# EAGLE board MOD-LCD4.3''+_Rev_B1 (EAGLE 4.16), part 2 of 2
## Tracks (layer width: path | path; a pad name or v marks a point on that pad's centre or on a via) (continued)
MCIDAT0  (via drill 0.4) (continued)
  Route2 0.25: v95.25,45.45 96.2,44.5 96.2,38.5 96.7,38 96.7,29.6 97.1,29.2 97.1,22.66 98.3,21.46 v98.3,16.89
  Bottom 0.25: v95.25,45.45 94.55,46.15 91.25,46.15 83,54.4 79.6,54.4 79.2,54.8 U2.171
  Bottom 0.508: MICRO_SD.7 98.3,15.41 v98.3,16.89 98.3,17.14 97.24,18.2 R14.2
MCIDAT1  (via drill 0.4)
  Top 0.25: v72.4,60.85 72.8,60.85 74.05,59.6 86.6,59.6 87.1,59.1 91.2,59.1 v91.6,59.5
  Route2 0.25: v91.6,59.5 91.9,59.2 91.9,52.1 96.7,47.3 96.7,38.7 97.2,38.2 97.2,29.8 97.6,29.4 97.6,22.9 99.19,21.31 99.19,17.14 v99.44,16.89
  Bottom 0.25: U2.153 73.3,62.4 72.4,61.5 v72.4,60.85
  Bottom 0.508: R18.2 99.44,18.03 v99.44,16.89 99.44,15.39 MICRO_SD.8
MCIDAT2  (via drill 0.4)
  Route2 0.25: v92.33,17.14 93,17.82 93,49.6 90.6,52 v90.6,58.35
  Bottom 0.25: U2.163 78.3,58.8 79,58.1 86.1,58.1 86.7,57.5 89.75,57.5 v90.6,58.35
  Bottom 0.508: MICRO_SD.1 91.73,16.55 v92.33,17.14 92.58,17.4 92.58,18.04 R20.2
MCIDAT3  (via drill 0.4)
  Route2 0.25: v90.81,17.02 90.81,17.65 92.5,19.35 92.5,49.4 89.75,52.15 89.75,59.8 v89.7,59.85
  Bottom 0.25: U2.157 78.8,61.8 80,60.6 88.95,60.6 v89.7,59.85 | 92.83,14.47 92.33,13.97 91.19,13.97 90.81,14.35 v90.81,17.02
  Bottom 0.508: v90.81,17.02 90.81,18.09 R9.2 | 92.83,14.47 MICRO_SD.2
MCIPWR  (via drill 0.4)
  Top 0.25: v93.7,59.35 93.7,60 92,61.7 85.4,61.7 84.8,61.1 76.8,61.1 v75.85,62.05
  Bottom 0.25: v75.85,62.05 74.8,63.1 U2.156
  Bottom 0.4: R6.2 R8.2 92.5,53.6 92.5,58.15 v93.7,59.35
MISO  (via drill 0.4, 0.6)
  Top 0.25: v58.45,60.5 58.15,60.8 56.8,60.8 56.2,61.4 47.55,61.4 46.95,62 36.4,62 34.8,60.4 7.2,60.4 4.3,57.5 4.3,55.8 2.3,53.8 2.3,49.7 4.5,47.5 v11.7,47.5
  Bottom 0.25: v58.45,60.5 58.45,61.83 59.8,63.17 U2.126
  Bottom 0.4: 11.16,43.96 11.7,44.5 v11.7,47.5
  Bottom 1: 11.16,43.96 UEXT.7
MMC_VDD  (via drill 0.4)
  Route2 0.25: v97.03,21.34 96.9,21.21 v96.9,16.89
  Bottom 0.508: C6.2 98.17,26.2 98.17,23.87 L1.1 97.03,22.73 v97.03,21.34 | v96.9,16.89 95.38,16.89 95.03,16.54 MICRO_SD.4
MOSI  (via drill 0.4, 0.6)
  Top 0.25: v4.5,45 4.5,45.8 1.3,49 1.3,54.4 3.1,56.2 3.1,58.1 6.4,61.4 34.4,61.4 36,63 47.2,63 47.8,63.6 52.9,63.6 53.63,62.87 57.84,62.87 v58.1,62.6
  Bottom 0.25: v58.1,62.6 58.8,63.3 U2.124
  Bottom 0.5: UEXT.8 4.06,43.96 4.5,44.4 v4.5,45
N$1  (via drill 0.4)
  Top 0.4: v94.9,62.4 94.9,61 96.5,59.4 v97.9,59.4
  Bottom 0.25: 82.8,63.9 U3.2
  Bottom 0.4: v97.9,59.4 98.4,58.9 L3.1 | v94.9,62.4 94.3,61.8 83.5,61.8 82.6,62.7 82.6,63.7 82.8,63.9
  Bottom 1.016: C50.2 96.56,54.44 97.6,53.4 L3.1
N$2
  Bottom 0.25: U2.44 53.3,28.6 52.67,27.98 52.38,27.98 R36.2
  Bottom 0.8: C12.2 47.2,24.5 48.5,24.5 | 48.5,24.5 48.9,24.5 R36.2 | Q1.1 48.5,24.5
N$3
  Bottom 0.4: VDDA_E.2 L5.2
N$4  (via drill 0.4, 0.6)
  Top 0.4: v54.35,17.9 54.8,17.45 70.55,17.45 71.9,16.1 82.18,16.1 82.97,16.89 86.55,16.89 v90.73,21.07
  Bottom 0.25: v90.73,21.07 90.5,21.3 LCD.2
  Bottom 0.4: T3.3 55.55,18.3 54.75,18.3 v54.35,17.9
N$5
  Bottom 0.6: R5.2 56.9,14.8 | 56.9,14.8 R11.2 | 56.9,14.8 T3.1
N$6
  Bottom 0.6: R11.1 59.95,13.1 T4.3
N$7
  Bottom 0.25: R36.1 52.3,29.6 U2.46
  Bottom 0.8: 48.5,28.8 Q1.2 | C14.2 48.5,28.8 | 48.5,28.8 49.9,28.8 50.4,29.3 R36.1
N$8
  Bottom 0.25: Q2.2 58.3,30.73 U2.34
  Bottom 0.6: C15.2 58.3,25.7 57.87,26.13 Q2.2
N$9
  Bottom 0.25: U2.36 57.3,32.8 55.8,31.3 55.8,30.77 Q2.1
  Bottom 0.6: Q2.1 55.33,26.43 54.6,25.7 C16.2
N$10
  Bottom 0.6: 59.3,17.3 T4.1 | R39.2 59.3,17.3 | 59.3,17.3 R21.1
N$11
  Bottom 0.5: 6.2,61.78 3.3V_UEXT_E.1 | UEXT.1 7.3,51.58 7.3,59.8 7.2,59.9 R2.2
  Bottom 0.762: R1.2 3.05,59.9 3.05,59.91 R23.2 5.21,59.91 5.21,59.9 R2.2
  Bottom 0.8: R2.2 6.2,61.78
N$12  (via drill 0.4)
  Top 0.25: v103.85,57.7 103.75,57.6 102.7,57.6 102,58.3 99.65,58.3 99.45,58.1 93.05,58.1 92.4,58.75 92.4,59.9 91.6,60.7 85.8,60.7 85.2,60.1 76.08,60.1 74.58,61.6 69.2,61.6 v68.42,60.83
  Bottom 0.25: v103.85,57.7 104.55,57 105.35,57 105.53,56.83 | v68.42,60.83 68.8,61.2 U2.144
  Bottom 0.6: 105.53,56.83 EXT1.6
N$13  (via drill 0.4, 0.6)
  Top 0.25: v66.92,59.83 67.72,59.83 67.95,59.6 71.1,59.6 72.1,58.6 86.1,58.6 87.6,57.1 99,57.1 99.3,56.8 103.2,56.8 103.38,56.98 105.38,56.98 106.8,55.55
  Top 0.4: 106.8,55.55 v113.3,55.55
  Bottom 0.25: v66.92,59.83 67.2,60.1 67.2,61.15 66.8,61.55 U2.140
  Bottom 0.4: v113.3,55.55 EXT1.7
N$14  (via drill 0.4)
  Top 0.25: v105.03,56.05 104.58,56.5 103.6,56.5 103.4,56.3 99.1,56.3 98.8,56.6 87.4,56.6 85.9,58.1 71.9,58.1 70.9,59.1 66.6,59.1 66.35,59.35 51.55,59.35 v50.8,60.1
  Bottom 0.25: v50.8,60.1 U2.108
  Bottom 0.6: v105.03,56.05 105.52,55.55 EXT1.8
N$15  (via drill 0.4, 0.6)
  Top 0.25: v49.1,54.4 49.9,53.6 71.4,53.6 73.4,55.6 98.3,55.6 98.6,55.3 103.4,55.3 103.7,55 106.28,55 107,54.28
  Top 0.4: 107,54.28 v113.3,54.28
  Bottom 0.25: U2.91 48.2,55.3 v49.1,54.4
  Bottom 0.4: v113.3,54.28 EXT1.9
N$16
  Bottom 0.25: 94.1,47.7 T2.1
  Bottom 0.4: 94.1,47.7 R15.2 91.9,48 91.5,48 91.1,48.4 91.1,50.5 R8.1
N$17  (via drill 0.4)
  Top 0.25: v104.03,55.73 103.95,55.8 98.9,55.8 98.6,56.1 73.2,56.1 71.2,54.1 55.5,54.1 v53.5,56.1
  Bottom 0.25: v53.5,56.1 51.5,58.1 50.1,58.1 48.9,59.3 U2.99
  Bottom 0.6: EXT1.10 105.28,54.28 104.03,55.55 v104.03,55.73
N$18  (via drill 0.4, 0.6)
  Top 0.25: 107.4,53.02 105.92,54.5 103.5,54.5 103.2,54.8 98.4,54.8 98.1,55.1 73.6,55.1 71.6,53.1 53,53.1 52.45,52.55 v51.15,52.55
  Top 0.4: 107.4,53.02 v113.3,53.02
  Route2 0.25: v48.8,43.3 48.5,43.6 48.5,49.9 v51.15,52.55
  Bottom 0.25: U2.67 v48.8,43.3
  Bottom 0.4: v113.3,53.02 EXT1.11
N$19  (via drill 0.4)
  Top 0.25: v51.85,50.35 52.55,50.35 53.8,51.6 72.2,51.6 74.2,53.6 97.5,53.6 97.8,53.3 102.6,53.3 102.9,53 104.1,53 v104.45,52.65
  Bottom 0.25: v51.85,50.35 51.1,49.6 50,49.6 49.3,50.3 U2.81
  Bottom 0.6: v104.45,52.65 104.81,53.02 EXT1.12
N$20  (via drill 0.4, 0.6)
  Top 0.25: 108.04,51.74 107.86,51.74 105.6,54 103.3,54 103,54.3 98.2,54.3 97.9,54.6 73.8,54.6 71.8,52.6 53.2,52.6 52.4,51.8 50,51.8 v49.5,52.3
  Top 0.4: 108.04,51.74 v113.3,51.74
  Bottom 0.25: U2.85 v49.5,52.3
  Bottom 0.4: v113.3,51.74 EXT1.13
N$21  (via drill 0.4)
  Top 0.25: v104.7,51.6 104.6,51.5 103,51.5 102.2,52.3 97.3,52.3 97,52.6 74.6,52.6 72.6,50.6 60.8,50.6 v60.4,50.2
  Bottom 0.25: U2.64 48,41.8 48.3,41.5 51.4,41.5 54.5,44.6 54.5,46.3 58.4,50.2 v60.4,50.2
  Bottom 0.6: EXT1.14 104.84,51.74 v104.7,51.6
N$22  (via drill 0.4, 0.6)
  Top 0.25: 108.4,50.48 105.38,53.5 103.1,53.5 102.8,53.8 98,53.8 97.7,54.1 74,54.1 72,52.1 53.5,52.1 52.6,51.2 43.96,51.2 43.66,50.9 40.3,50.9
  Top 0.254: v37.4,48.2 38.26,49.06 39.16,49.06 39.85,49.75 39.85,50.45 40.3,50.9
  Top 0.4: 108.4,50.48 v113.3,50.48
  Route2 0.254: v36.8,35.8 36.8,41.9 37.8,42.9 37.8,44.9 37.4,45.3 v37.4,48.2
  Bottom 0.254: U2.54 44.5,36.8 43.7,36 38.8,36 38.6,35.8 v36.8,35.8
  Bottom 0.4: v113.3,50.48 EXT1.15
N$23  (via drill 0.4)
  Top 0.25: v56.8,47.4 57.5,48.1 60.8,48.1 61.3,47.6 67.9,47.6 68.83,48.52 84.03,48.52 84.6,49.1 97,49.1 97.9,48.2 102.83,48.2 v102.95,48.33
  Bottom 0.25: U2.57 49,38.3 55.3,44.6 55.3,45.9 v56.8,47.4 | v102.95,48.33 102.95,49.75 103.67,50.48
  Bottom 0.6: 103.67,50.48 EXT1.16
N$24  (via drill 0.4, 0.6)
  Top 0.25: v61.33,49.8 61.62,50.1 76.25,50.1 77.75,51.6 96.6,51.6 98.5,49.7 101.2,49.7 101.8,50.3 107.32,50.3 108.42,49.2 108.49,49.2
  Top 0.4: 108.49,49.2 v113.3,49.2
  Bottom 0.25: U2.47 51.8,40.27 v61.33,49.8
  Bottom 0.4: v113.3,49.2 EXT1.17
N$25  (via drill 0.4)
  Top 0.25: v62.2,48.35 67.85,48.35 68.5,49 83.8,49 84.35,49.55 97.25,49.55 98.1,48.7 101.8,48.7 102.2,49.1 103.25,49.1 103.65,48.7 104.3,48.7 v105.1,49.5
  Bottom 0.25: U2.31 59.8,34.8 59.5,35.1 59.5,36 59.8,36.3 60.7,36.3 61.5,37.1 61.5,39.8 61.3,40 61.3,46.9 62.2,47.8 v62.2,48.35
  Bottom 0.6: v105.1,49.5 105.39,49.2 EXT1.18
N$26  (via drill 0.4, 0.6)
  Top 0.25: v60.38,47.38 60.65,47.1 68.2,47.1 69.15,48.05 84.15,48.05 84.7,47.5 85.5,47.5 86.1,48.1 96.6,48.1 97.6,47.1 105.54,47.1 106.37,47.94 108.56,47.94
  Top 0.4: 108.56,47.94 v113.3,47.94
  Bottom 0.25: U2.39 55.8,35.2 56,35.4 56,36.2 55.6,36.6 55.15,36.6 54.4,37.35 54.4,41.4 v60.38,47.38
  Bottom 0.4: v113.3,47.94 EXT1.19
N$27  (via drill 0.4)
  Top 0.25: v79.42,49.77 83.83,49.77 84.05,50 97.5,50 98.3,49.2 101.5,49.2 101.9,49.6 103.8,49.6 v103.9,49.5
  Route2 0.25: v65.2,61 65.6,61 66.25,61.65 74.65,61.65 78.7,57.6 78.7,50.5 v79.42,49.77
  Bottom 0.25: v65.2,61 64.8,61.4 64.8,62.3 65.3,62.8 U2.137
  Bottom 0.6: v103.9,49.5 103.9,49.4 105.36,47.94 EXT1.20
N$28  (via drill 0.4, 0.6)
  Top 0.25: v68.05,62.4 68.3,62.4 68.7,62.8 78.6,62.8 78.8,62.6 93.5,62.6 94.1,63.2 98.1,63.2 98.3,63 v103.6,63
  Route2 0.25: v113.3,46.66 111.94,46.66 108.1,50.5 108.1,57.4 103.6,61.9 v103.6,63
  Bottom 0.25: v68.05,62.4 68.3,62.65 U2.143
  Bottom 0.4: v113.3,46.66 EXT1.21
N$29
  Bottom 0.508: 25.71,19.22 25.78,19.29 25.78,19.3 24.64,19.3 24.38,19.05 | VR2.1 21.59,16.89 22.23,16.89
  Bottom 0.559: VR2.1 21.59,16.13 21.84,16.13
  Bottom 1.016: L2.1 26.11,16.13 23.37,16.13 | 21.84,16.13 23.37,16.13 | 23.37,16.13 C51.1 25.71,19.22 26.04,19.22 | 26.04,19.3 D6.1 26.04,19.22 | 26.04,19.22 26.07,19.18
  Bottom 1.27: 25.71,19.22 25.4,19.22 25.4,16.38 24.38,16.38 24.38,19.05 | 22.23,16.89 23.24,16.89
N$30  (via drill 0.4)
  Route2 0.25: v95.8,61.7 95.8,61.1 96.65,60.25 99.65,60.25 100.7,59.2 100.7,51.8 v100.97,51.52
  Bottom 0.25: U2.151 72.3,64.7 73.1,65.5 74.8,65.5 77.8,62.5 78.85,62.5 80.25,61.1 95.2,61.1 v95.8,61.7 | v100.97,51.52 101.17,51.52 101.7,51 101.7,47.3 102.33,46.66 105.41,46.66
  Bottom 0.6: 105.41,46.66 EXT1.22
N$31
  Bottom 0.559: R29.2 47.62,2.96 47.62,2.86 U5.3
  Bottom 1.016: R29.2 48.51,2.96 48.51,2.92 R26.1
N$32  (via drill 0.4, 0.6)
  Route2 0.25: v113.3,45.4 111.91,45.4 107.4,49.9 107.4,57.1 103,61.5 102.1,61.5 101.7,61.1 v96.85,61.1
  Bottom 0.25: U2.161 78.7,59.8 79.4,59.1 86.5,59.1 87,58.6 88.1,58.6 88.6,59.1 90.1,59.1 91.6,60.6 96.35,60.6 v96.85,61.1
  Bottom 0.4: v113.3,45.4 EXT1.23
N$33  (via drill 0.4)
  Top 0.25: v104.9,45.8 104.6,46.1 97.2,46.1 96.65,46.65 84.85,46.65 84.1,47.4 73.35,47.4 v73.25,47.3
  Route2 0.25: v73.25,47.3 73,47.55 73,53.2 74.15,54.35 v74.15,56.85
  Bottom 0.25: U2.167 76.17,56.8 75.47,56.1 74.4,56.1 74.15,56.35 v74.15,56.85
  Bottom 0.6: v104.9,45.8 105.31,45.4 EXT1.24
N$34  (via drill 0.4, 0.6)
  Top 0.25: v87.75,47.38 87.97,47.6 96.4,47.6 97.4,46.6 105.6,46.6 108.08,44.12 109.38,44.12
  Top 0.4: 109.38,44.12 v113.3,44.12
  Bottom 0.25: U2.175 79.6,52.8 82.4,50 86,50 87.75,48.25 v87.75,47.38
  Bottom 0.4: v113.3,44.12 EXT1.25
N$35
  Bottom 0.61: R54.2 15.88,17.02 17.27,17.02 17.78,16.51 VR2.4
  Bottom 1.016: R50.1 15.88,18.92 R54.2
N$36  (via drill 0.4)
  Top 0.25: v73.3,46.3 78,46.3 78.6,46.9 83.88,46.9 84.58,46.2 96.4,46.2 97,45.6 103.6,45.6 v104.3,44.9
  Bottom 0.25: U2.195 76.3,42.8 76.1,42.6 76.1,41.5 75.2,40.6 74.6,40.6 72.4,42.8 72.4,45.4 v73.3,46.3
  Bottom 0.4: v104.3,44.9 104.7,44.5 105.3,44.5 105.67,44.12
  Bottom 0.6: 105.67,44.12 EXT1.26
N$37  (via drill 0.4, 0.6)
  Top 0.25: v49.05,42.3 50.79,40.56 79.24,40.56 80.6,39.2 87.1,39.2 87.5,39.6 102.4,39.6 103.85,41.05 107.35,41.05 109.16,42.85 109.5,42.85
  Top 0.4: 109.5,42.85 v113.3,42.85
  Bottom 0.25: U2.65 v49.05,42.3
  Bottom 0.4: v113.3,42.85 EXT1.27
N$38  (via drill 0.4)
  Top 0.25: v104.42,40.3 103.8,40.3 102.6,39.1 87.7,39.1 87.3,38.7 80.4,38.7 79.04,40.06 50.26,40.06 47.8,37.6 v45.7,37.6
  Bottom 0.25: EXT1.28 105.75,42.85 105.1,42.2 105.1,41.6 104.42,40.92 v104.42,40.3 | v45.7,37.6 45.7,38.1 46.4,38.8 U2.58
N$39  (via drill 0.4, 0.6)
  Top 0.25: 109.63,41.59 108.69,41.59 105.67,38.58 103.58,38.58 103.1,38.1 88.1,38.1 87.7,37.7 80,37.7 78.64,39.06 52.26,39.06 v51,37.8
  Top 0.4: 109.63,41.59 v113.3,41.59
  Bottom 0.25: U2.56 v51,37.8
  Bottom 0.4: v113.3,41.59 EXT1.29
N$40  (via drill 0.4)
  Top 0.25: v104.45,39.3 103.55,39.3 102.85,38.6 87.9,38.6 87.5,38.2 80.2,38.2 78.84,39.56 51.46,39.56 v48.9,37
  Bottom 0.25: EXT1.30 105.78,41.59 105.2,41 105.2,39.8 104.7,39.3 v104.45,39.3 | U2.55 48.6,37.3 v48.9,37
N$41  (via drill 0.4, 0.6)
  Top 0.25: v74.2,37.75 78.4,37.75 79.45,36.7 88.15,36.7 88.55,37.1 105,37.1 108.22,40.31 109.63,40.31
  Top 0.4: 109.63,40.31 v113.3,40.31
  Bottom 0.25: v74.2,37.75 75.25,38.8 U2.203
  Bottom 0.4: v113.3,40.31 EXT1.31
N$42
  Bottom 0.5: RM2.3.2 35.38,41.22 34.99,41.61
  Bottom 1: JTAG.17 34.99,41.61
N$43
  Bottom 0.4: 96.3,46.7 91.5,46.7 90.1,48.1 R6.1 | 96.3,46.7 R7.2 | 96.3,46.7 96.3,48.45 T2.3
N$44  (via drill 0.4)
  Top 0.25: v73.08,35.75 73.33,36 77.92,36 78.72,35.2 88.8,35.2 89.2,35.6 108.2,35.6 v109.6,34.2
  Bottom 0.25: U2.5 72.8,34 | 72.8,34 72.8,33.9 | 72.8,34 72.8,35.48 v73.08,35.75
  Bottom 0.4: EXT1.32 108.19,40.31 109,39.5 109,34.8 v109.6,34.2
N$45  (via drill 0.4, 0.6)
  Top 0.25: v69.63,36.73 69.9,37 78.4,37 79.2,36.2 88.4,36.2 88.8,36.6 105.3,36.6 107.75,39.05 109.63,39.05
  Top 0.4: 109.63,39.05 v113.3,39.05
  Bottom 0.25: U2.11 69.8,36.55 v69.63,36.73
  Bottom 0.4: v113.3,39.05 EXT1.33
N$46  (via drill 0.4)
  Top 0.25: v68.25,38.25 68.5,38.5 78.4,38.5 79.7,37.2 87.9,37.2 88.3,37.6 104.2,37.6 v104.44,37.84
  Bottom 0.25: U2.19 65.8,36.08 67.97,38.25 v68.25,38.25 | v104.44,37.84 105.64,39.05
  Bottom 0.6: 105.64,39.05 EXT1.34
N$47  (via drill 0.4, 0.6)
  Top 0.25: v64.25,38.28 64.27,38.28 67.3,35.25 69.75,35.25 71,36.5 78.2,36.5 79,35.7 88.6,35.7 89,36.1 105.5,36.1 107.17,37.77 109.63,37.77
  Top 0.4: 109.63,37.77 v113.3,37.77
  Bottom 0.25: U2.25 62.8,35.1 62.47,35.43 62.47,37.75 63,38.28 v64.25,38.28
  Bottom 0.4: v113.3,37.77 EXT1.35
N$48  (via drill 0.4)
  Top 0.25: v75.8,51.8 76.1,52.1 96.8,52.1 98.42,50.48 v100.9,50.48
  Bottom 0.25: v75.8,51.8 75.8,53.5 76.1,53.8 U2.173 | 105.67,37.77 105,37.1 103.9,37.1 101.6,39.4 101.6,46.5 100.9,47.2 v100.9,50.48
  Bottom 0.6: 105.67,37.77 EXT1.36
N$49  (via drill 0.4, 0.6)
  Route2 0.25: v45.8,59.95 45.8,59.2 46.5,58.5 46.5,41.6 47,41.1 47,35.5 47.4,35.1 47.4,14.34 61.03,0.7 97.8,0.7 114.4,17.3 114.4,36.01 v113.9,36.51
  Bottom 0.25: v45.8,59.95 46.15,60.3 U2.101
  Bottom 0.4: v113.9,36.51 EXT1.37
N$50  (via drill 0.4)
  Route2 0.25: v49.77,60.17 47.5,57.9 47.5,42 48,41.5 48,36 48.4,35.6 48.4,14.81 61.51,1.7 97.2,1.7 106.4,10.9 106.4,32 104.9,33.5 v104.9,34.3
  Bottom 0.25: v49.77,60.17 48.15,61.8 U2.104
  Bottom 0.6: EXT1.38 105.41,36.51 104.9,36 v104.9,34.3
N$51  (via drill 0.4, 0.6)
  Route2 0.25: v49,62.85 47,60.85 47,41.8 47.5,41.3 47.5,35.7 47.9,35.3 47.9,14.63 61.34,1.2 97.5,1.2 113.9,17.6 113.9,34.63 v113.3,35.23
  Bottom 0.25: U2.105 49.3,63.15 v49,62.85
  Bottom 0.4: v113.3,35.23 EXT1.39
N$52
  Bottom 0.8: R30.2 16.5,50.1 17.4,51 T5.3
N$53  (via drill 0.4)
  Top 0.25: v52.3,62.67 52.58,62.4 56.7,62.4 57.3,61.8 58.7,61.8 59.7,62.8 66.3,62.8 67.5,61.6 68.4,61.6 68.9,62.1 74.75,62.1 76.25,60.6 85,60.6 85.6,61.2 91.8,61.2 92.9,60.1 92.9,59 93.3,58.6 99.3,58.6 99.5,58.8 102.67,58.8 v103.1,58.38
  Route2 0.25: v103.1,58.38 103.1,55.4 105.9,52.6 105.9,47 108.2,44.7 108.2,34.4 v108.5,34.1
  Bottom 0.25: v52.3,62.67 U2.111 | EXT1.40 106.8,35.23
  Bottom 0.4: v108.5,34.1 108.2,34.4 108.2,34.8 107.77,35.23 EXT1.40
N$54
  Bottom 0.8: 12.9,51.4 T5.1 | 12.9,51.4 R27.2 | R31.2 12.9,51.4
N$55  (via drill 0.4)
  Route2 0.25: v54.23,66.08 55.12,66.97 80.97,66.97 82.05,65.9 83.5,65.9 84.58,66.97 92.53,66.97 93.5,66 93.5,62.7 98.7,57.5 98.7,39.6 99.2,39.1 99.2,31.18 v99.67,30.7
  Bottom 0.25: U2.123 58.3,64.8 57.77,65.33 57.77,66.03 57.45,66.35 54.5,66.35 v54.23,66.08
  Bottom 0.4: v99.67,30.7 104.5,30.7 105.38,29.82
  Bottom 0.6: 105.38,29.82 EXT2.6
N$56  (via drill 0.4, 0.6)
  Top 0.25: 91.45,35.1 90.47,35.1 v90.23,34.86 | 110.3,30.8 110.3,29.27 111.02,28.55 111.53,28.55
  Top 0.254: 91.45,35.1 106,35.1 110.3,30.8
  Top 0.4: 111.53,28.55 v112.9,28.55
  Route2 0.254: v61.02,61.98 63.42,61.98 65.45,64 77.7,64 79.2,65.5 80.3,65.5 87.2,58.6 87.2,51.9 90.5,48.6 90.5,35.13 v90.23,34.86
  Bottom 0.254: v61.02,61.98 61.3,62.25 U2.129
  Bottom 0.6: v112.9,28.55 EXT2.7
N$57  (via drill 0.4)
  Top 0.25: v73.65,43.65 78.55,43.65 79.5,42.7 85.8,42.7 86.8,43.7 92,43.7 93.6,42.1 98.4,42.1 98.9,42.6 102,42.6 v103,43.6
  Route2 0.25: v103,43.6 102.7,43.3 102.7,33.6 104.2,32.1 v104.2,29.6
  Bottom 0.25: v73.65,43.65 74.55,44.55 74.55,47.65 75.7,48.8 U2.183
  Bottom 0.6: EXT2.8 105.25,28.55 v104.2,29.6
N$58
  Bottom 0.762: SD.A 103.5,3.55 R17.2
N$59
  Bottom 0.4: 22.15,64.7 USB.GND4 | 12.25,64.7 USB.GND2 12.25,57.65 C13.2 | 12.25,64.7 USB.GND1 | 22.15,64.7 USB.GND3 | 12.25,64.7 22.15,64.7
N$60
  Bottom 0.762: USB_D_LINK.A 9.65,61.45 R3.1
N$61  (via drill 0.4)
  Route2 0.4: v95.8,33.85 96.1,33.55 96.1,29.3 96.4,29 96.4,22.6 96.01,22.21 v96.01,19.94 96.01,13.54 97.35,12.2 v98.4,12.2
  Bottom 0.4: R16.2 105.92,4.57 103.67,6.82 R17.1 103.21,7.11 100.97,7.11 98.4,9.68 v98.4,12.2 | L1.2 99.2,23.12 99.2,21.98 98.3,21.08 98.3,19.9 | C3.2 94.5,36.7 95.3,36.7 95.8,36.2 v95.8,33.85 | 98.3,19.9 R18.1 | R14.1 98.3,19.9
  Bottom 0.508: R20.1 R10.1 94.88,19.94 v96.01,19.94 97.14,19.94 R14.1
  Bottom 0.6: C3.2 94.2,39.8 | 94.2,39.8 T1.3 | C1.2 92.3,39.8 94.2,39.8
N$62
  Bottom 0.25: T1.1 96.5,41.1
  Bottom 0.6: C1.1 92.3,41.5 96.3,41.5 | 96.3,41.5 96.4,41.4 T1.1 | 96.3,41.5 R7.1 | 96.5,41.1 R4.2
N$63  (via drill 0.4, 0.6)
  Top 0.25: 110.74,27.29 102.61,27.29 102.1,27.8 98.1,27.8 96.2,29.7 94.9,29.7 92.47,32.12 89.47,32.12 86.9,34.7 78.22,34.7 78.02,34.5 67.35,34.5 64.37,37.48 v63.25,37.48
  Top 0.4: 110.74,27.29 v113,27.29
  Route2 0.25: v63.25,37.48 63.25,39.25 63.5,39.5 63.5,55.05 v63.2,55.35
  Bottom 0.25: 56.3,62.1 U2.119 56.3,61.3 56.55,61.05 56.55,59.55 59.4,56.7 61.85,56.7 v63.2,55.35
  Bottom 0.6: v113,27.29 EXT2.9
N$64
  Bottom 1.016: R52.2 C49.2
N$65
  Bottom 0.559: VR2.8 21.68,21.84 21.97,21.84 | 23.37,21.34 C51.2
  Bottom 1.016: 21.97,21.84 22.86,21.84 23.37,21.34
N$66  (via drill 0.4)
  Top 0.25: v66.4,60.7 67.5,60.7 68.1,60.1 72.83,60.1 73.83,59.1 86.3,59.1 87.8,57.6 99.9,57.6 v99.95,57.55
  Route2 0.25: v99.95,57.55 99.7,57.3 99.7,45.8 100.4,45.1 100.4,42.4 99.7,41.7 99.7,40 100.2,39.5 100.2,32.3 101,31.5 v101,29.6
  Bottom 0.25: v66.4,60.7 66.3,60.8 U2.139 | v101,29.6 102.6,28 104.75,28 105.47,27.29
  Bottom 0.6: 105.47,27.29 EXT2.10
N$67
  Bottom 0.8: VR1(3.3V).1 19.01,35.1 R43.1 R45.2
N$69
  Bottom 0.559: C48.1 VR2.3
  Bottom 1.016: C49.1 18.03,14.19 C48.1
N$70
  Bottom 0.635: VR2.2 20.32,15.37 20.83,14.86 20.83,14.44 R22.2
  Bottom 1.016: R22.2 22.1,14.19 R51.1
N$71  (via drill 0.4, 0.6)
  Top 0.25: v104.9,25.8 110.69,25.8 110.9,26.02 | v81.2,44.6 83.9,44.6 84.55,45.25 92.85,45.25 93.4,44.7 97.1,44.7 97.5,45.1 102.72,45.1 v103.1,44.73
  Top 0.4: 110.9,26.02 v113,26.02
  Route2 0.25: v103.1,44.73 103.8,44.02 103.8,43 103.2,42.4 103.2,33.8 105,32 105,25.9 v104.9,25.8
  Bottom 0.25: U2.187 78.6,46.8 80.3,45.1 80.7,45.1 v81.2,44.6
  Bottom 0.6: v113,26.02 EXT2.11
N$72  (via drill 0.4)
  Top 0.25: v90.25,32.85 92.45,32.85 95.1,30.2 96.5,30.2 98.1,28.6 v100.9,28.6
  Bottom 0.25: U2.193 78.1,43.8 80.2,41.7 87.4,41.7 90.1,39 90.1,36.05 91.1,35.05 91.1,33.1 90.85,32.85 v90.25,32.85 | v100.9,28.6 102.1,27.4 104.4,27.4 105.78,26.02 EXT2.12
N$73  (via drill 0.4, 0.6)
  Top 0.25: v60.25,37.67 60.25,37.17 62.67,34.75 66.27,34.75 67.02,34 77.9,34 81.35,30.55 84.15,30.55 84.8,29.9 84.8,29.6 87.35,27.05 94.75,27.05 95.1,26.7 101.6,26.7 103.56,24.75 110.9,24.75
  Top 0.4: 110.9,24.75 v113,24.75
  Bottom 0.25: U2.37 56.8,34.8 57,35 57,35.48 59.2,37.67 v60.25,37.67
  Bottom 0.6: v113,24.75 EXT2.13
N$74
  Bottom 0.635: VR2.6 19.05,23.24 18.63,23.66 R28.2
N$75  (via drill 0.4)
  Top 0.25: v100.95,24 100.45,24.5 87.6,24.5 84.1,28 83.1,28 77.57,33.53 66.7,33.53 66.07,34.15 56.9,34.15 v55.27,35.77
  Bottom 0.25: U2.40 55.3,35.75 v55.27,35.77
  Bottom 0.4: v100.95,24 102.45,24 103.19,24.75
  Bottom 0.6: 103.19,24.75 EXT2.14
N$76  (via drill 0.4, 0.6)
  Top 0.25: v52.1,17.6 53.2,17.6 53.9,16.9 70.3,16.9 71.7,15.5 77.1,15.5 79.6,13 85.53,13 87.53,15 103.87,15 v104.27,14.61 | v104.15,23.4 104.22,23.48 110.9,23.48
  Top 0.4: 110.9,23.48 v113,23.48
  Route2 0.25: v52.7,37.25 52.5,37.25 51.4,36.15 51.4,32.7 52.4,31.7 52.4,17.9 v52.1,17.6 | v104.27,14.61 103.9,14.97 103.9,23.15 v104.15,23.4
  Bottom 0.25: U2.42 54.3,34.9 54,35.2 54,36.15 52.9,37.25 v52.7,37.25
  Bottom 0.6: v113,23.48 EXT2.15
N$77  (via drill 0.4)
  Top 0.25: v85.17,48.27 85.5,48.6 96.8,48.6 97.8,47.6 103.6,47.6 v103.9,47.9
  Route2 0.25: v103.9,47.9 104.2,47.9 107.7,44.4 107.7,33.5 109,32.2 v109,29.2
  Bottom 0.25: U2.178 78.95,51.3 81.97,48.27 v85.17,48.27
  Bottom 0.4: EXT2.16 108.58,23.48 109,23.9 v109,29.2
N$79  (via drill 0.4, 0.6)
  Top 0.25: v91.72,26.27 92,26 101.5,26 102.7,24.8 102.7,23.6 104.09,22.2 110.9,22.2
  Top 0.4: 110.9,22.2 v113,22.2
  Route2 0.25: v89.75,42.95 89.75,42.05 89.4,41.7 89.4,30.2 89.47,30.12 89.47,27.62 90.83,26.27 v91.72,26.27
  Bottom 0.25: U2.180 77.85,50.3 80.35,47.8 84.5,47.8 87.33,44.97 87.73,44.97 v89.75,42.95
  Bottom 0.6: v113,22.2 EXT2.17
N$80  (via drill 0.4)
  Top 0.25: v73.5,44.67 78.28,44.67 79.75,43.2 84.1,43.2 85.08,44.17 92.22,44.17 92.8,43.6 99.33,43.6 v99.6,43.33
  Route2 0.25: v99.6,43.33 99.2,42.92 99.2,39.8 99.7,39.3 99.7,32.1 100.45,31.35 100.45,30.3 100.1,29.95 100.1,23.6 v101.08,22.62
  Bottom 0.25: v73.5,44.67 73.5,45.2 74.1,45.8 74.1,47.9 75.5,49.3 U2.182
  Bottom 0.6: v101.08,22.62 101.5,22.2 EXT2.18
N$82  (via drill 0.4, 0.6)
  Top 0.25: v73.85,42.65 74.4,43.2 78.3,43.2 79.3,42.2 87.7,42.2 88.3,41.6 98.7,41.6 99.2,42.1 102.6,42.1 104.2,43.7 v104.6,43.7
  Route2 0.25: v113,20.93 110.67,20.93 107.9,23.7 107.9,32.6 107.2,33.3 107.2,41.1 v104.6,43.7
  Bottom 0.25: v73.85,42.65 75,43.8 75,47.4 75.9,48.3 U2.184
  Bottom 0.6: v113,20.93 EXT2.19
N$83  (via drill 0.4)
  Top 0.25: v83.65,28.8 84.1,28.8 87.9,25 101.1,25 101.7,24.4 101.7,23.2 103.97,20.93 v105.17,20.93
  Route2 0.25: v70.3,57.83 75.58,57.83 77.7,55.7 77.7,40.7 80.3,38.1 80.3,33.05 81.7,31.65 81.7,30.7 83.6,28.8 v83.65,28.8
  Bottom 0.25: v70.3,57.83 U2.147
  Bottom 0.6: v105.17,20.93 EXT2.20
N$84  (via drill 0.4, 0.6)
  Top 0.25: v74.85,42.4 78.4,42.4 79.1,41.7 87.5,41.7 88.1,41.1 99,41.1 99.5,41.6 102.75,41.6 103.85,42.7 v104.55,42.7
  Route2 0.25: v104.55,42.7 106.7,40.55 106.7,33.1 107.4,32.4 107.4,23.4 111.14,19.66 v113,19.66
  Bottom 0.25: v74.85,42.4 74.85,42.85 75.5,43.5 75.5,46.6 76.2,47.3 U2.186
  Bottom 0.6: v113,19.66 EXT2.21
N$85  (via drill 0.4)
  Top 0.25: v74.95,41.4 78.7,41.4 78.9,41.2 87.3,41.2 87.9,40.6 99.3,40.6 99.8,41.1 103.1,41.1 103.8,41.8 v104.1,41.8
  Route2 0.25: v105.15,19.66 105.9,20.41 105.9,31.8 103.7,34 103.7,41.4 v104.1,41.8
  Bottom 0.25: v74.95,41.4 75.6,42.05 75.6,42.8 76,43.2 76,46 76.3,46.3 U2.188
  Bottom 0.6: v105.15,19.66 EXT2.22
N$86  (via drill 0.4, 0.6)
  Top 0.25: v83.78,29.82 88.1,25.5 101.3,25.5 102.2,24.6 102.2,23.4 103.9,21.7 105.7,21.7 109,18.39 110.9,18.39
  Top 0.4: 110.9,18.39 v113,18.39
  Route2 0.25: v83.78,29.82 84,30.05 84,32.3 83.9,32.4 83.9,37.8 84.5,38.4 84.5,42.55 v85.4,43.45
  Bottom 0.25: v85.4,43.45 85.25,43.3 80.7,43.3 78.7,45.3 U2.190
  Bottom 0.6: v113,18.39 EXT2.23
N$87  (via drill 0.4)
  Top 0.25: 45.3,31.4 45.2,31.4 | 45.3,31.4 53.27,31.4 54.7,32.83 v62.5,32.83 | v42,31.1 42.3,31.4 45.3,31.4
  Bottom 0.25: 38.2,26.8 38.2,30 39.3,31.1 v42,31.1 | U2.24 63.3,33.33 62.8,32.83 v62.5,32.83
  Bottom 0.6: C19.2 38.2,26.8 L4.2
N$88  (via drill 0.4)
  Top 0.25: v90.25,31.38 92.53,31.38 94.7,29.2 95.9,29.2 97.8,27.3 101.8,27.3 102.55,26.55 v104.2,26.55
  Route2 0.25: v104.2,26.55 104.1,26.45 104.1,24.7 104.9,23.9 104.9,23 104.39,22.49 104.39,19.3 v105.16,18.54
  Bottom 0.25: U2.192 78.3,44.3 80.4,42.2 87.7,42.2 90.7,39.2 90.7,36.12 91.7,35.12 91.7,32.17 90.9,31.38 v90.25,31.38
  Bottom 0.6: EXT2.24 105.3,18.39 v105.16,18.54
N$89  (via drill 0.4)
  Top 0.25: v105.9,34 105.4,33.5 104.48,33.5 103.38,34.6 91.24,34.6 90.49,33.85 v90.25,33.85
  Route2 0.25: v105.9,34 105.9,33.2 106.9,32.2 106.9,23.1 109.2,20.8 v109.2,17.12
  Bottom 0.25: U2.194 77.9,43.3 80,41.2 87.1,41.2 89.37,38.93 89.37,34.37 89.9,33.85 v90.25,33.85
  Bottom 0.6: v109.2,17.12 EXT2.25
N$90  (via drill 0.4)
  Top 0.25: v80.7,40.45 80.95,40.7 87.1,40.7 87.7,40.1 100.2,40.1 v100.45,40.35
  Route2 0.25: v100.45,40.35 100.7,40.1 100.7,32.6 101.8,31.5 101.8,19.5 101.22,18.92 v101.09,18.92
  Bottom 0.25: v101.09,18.92 101.98,18.92 103.78,17.12 105.34,17.12 | v80.7,40.45 80.05,40.45 78.2,42.3 U2.196
  Bottom 0.6: 105.34,17.12 EXT2.26
N$91  (via drill 0.4, 0.6)
  Top 0.25: v53.13,6.1 53.48,5.75 73.44,5.75 74.04,6.35 100.08,6.35 100.73,5.7 105.1,5.7 105.6,6.2 v105.8,6.2
  Route2 0.25: v45.6,30.5 45.6,29.8 46.4,29 46.4,12.83 v53.13,6.1
  Bottom 0.25: U2.52 49.3,33.4 48.4,32.5 47.5,32.5 45.6,30.6 v45.6,30.5 | v105.8,6.2 108.15,6.2 109.22,7.28 109.22,15.43 109.66,15.86
  Bottom 0.6: 109.66,15.86 EXT2.27
N$92  (via drill 0.4, 0.6)
  Top 0.25: v53.03,7.5 54.28,6.25 73.18,6.25 73.79,6.86 100.33,6.86 100.99,6.2 104.5,6.2 105.4,7.1 v106.8,7.1
  Route2 0.25: v46.6,30.5 46.9,30.2 46.9,13.63 v53.03,7.5
  Bottom 0.25: U2.51 49.8,33.2 48.5,31.9 48,31.9 v46.6,30.5 | v106.8,7.1 108.3,7.1 108.78,7.58 108.78,15.43 108.34,15.86
  Bottom 0.6: 108.34,15.86 EXT2.28
N$93  (via drill 0.4, 0.6)
  Top 0.25: 110.9,13.31 107.94,13.31 100.3,20.95 100.3,21.8 98.1,24 87.28,24 84.67,26.6 82.37,26.6 77.17,31.8 76.91,31.8 72.59,31.8 71.67,32.73 v70.31,32.73
  Top 0.4: 110.9,13.31 v113.1,13.31
  Bottom 0.25: v70.31,32.73 70,32.73 69.3,33.43 U2.12
  Bottom 0.6: v113.1,13.31 EXT2.31
N$94  (via drill 0.4)
  Top 0.25: v101.47,16.76 101.22,16.76 99.8,18.18 99.8,21.5 97.8,23.5 87,23.5 84.4,26.1 82.2,26.1 77.06,31.24 72.35,31.24 71.84,31.75 69.81,31.75 v69.06,32.5
  Bottom 0.25: U2.14 68.3,33.03 68.83,32.5 v69.06,32.5 | 101.35,16.76 v101.47,16.76 102.62,16.76 103.25,16.13 103.25,13.97 103.91,13.31 105.39,13.31
  Bottom 0.6: 105.39,13.31 EXT2.32
N$95  (via drill 0.4)
  Route2 0.25: v57,65.5 57.7,64.8 59.3,64.8 60.5,66 73.6,66 75.1,64.5 77.4,64.5 78.9,66 80.5,66 85.8,60.7 90.1,60.7 90.65,60.15 90.65,59.35 91.4,58.6 91.4,51.9 93.5,49.8 93.5,23.9 93.7,23.7 93.7,12.37 95.05,11.02 98.52,11.02 v99.55,12.04
  Bottom 0.25: U2.122 57.8,64.65 57,65.45 v57,65.5
  Bottom 0.6: v99.55,12.04 EXT2.34
N$96  (via drill 0.4, 0.6)
  Top 0.25: 110.9,10.78 106.17,10.78 103.1,7.7 101.77,7.7 101.09,8.38 73.52,8.38 69.07,12.83 53.65,12.83 v52.47,14
  Top 0.4: 110.9,10.78 v113.1,10.78
  Route2 0.25: v52.47,14 52.47,14.67 53.4,15.6 53.4,32.7 52.7,33.4 v52.7,35.2
  Bottom 0.25: v52.7,35.2 52.8,35.1 U2.45
  Bottom 0.6: v113.1,10.78 EXT2.35
N$97  (via drill 0.4, 0.6)
  Top 0.25: v51.3,15.1 53.3,15.1 54,14.4 68.9,14.4 73.97,9.34 100.73,9.34 101.7,10.3 102.17,10.78
  Top 0.4: 102.17,10.78 v104.28,10.78
  Route2 0.25: v52.7,38.25 52.5,38.25 50.9,36.65 50.9,32.5 51.9,31.5 51.9,18.9 51.3,18.3 v51.3,15.1
  Bottom 0.25: U2.41 54.8,35.1 54.5,35.4 54.5,36.55 52.8,38.25 v52.7,38.25
  Bottom 0.6: v104.28,10.78 EXT2.36
N$98  (via drill 0.4, 0.6)
  Top 0.25: 110.9,9.51 106,9.51 103.7,7.2 101.51,7.2 100.84,7.87 73.33,7.87 72.72,8.48 70.78,8.48 v70.5,8.2
  Top 0.4: 110.9,9.51 v113.1,9.51
  Route2 0.25: v70.5,8.2 68.5,8.2 58.7,18 58.7,21.6 58,22.3 58,40.1 56.1,42 56.1,45.6 54.1,47.6 54.1,54 54.65,54.55 v54.65,56.05
  Bottom 0.25: v54.65,56.05 52.1,58.6 50.3,58.6 49.1,59.8 U2.100
  Bottom 0.4: v113.1,9.51 EXT2.37
N$99  (via drill 0.4, 0.6)
  Top 0.25: v56.8,50.85 57.05,51.1 72.4,51.1 74.4,53.1 97.2,53.1 97.5,52.8 102.4,52.8 102.95,52.25 v103.4,52.25
  Route2 0.25: v103.4,9.51 103.4,32.2 102.2,33.4 102.2,49.1 103.4,50.3 v103.4,52.25
  Bottom 0.25: U2.98 48.7,58.8 49.9,57.6 50.95,57.6 56.8,51.75 v56.8,50.85
  Bottom 0.6: v103.4,9.51 EXT2.38
N$100
  Bottom 0.762: PWR.C 98.42,44.65 R38.1
N$101  (via drill 0.4, 0.6)
  Top 0.25: 110.9,8.23 105.64,8.23 104.1,6.7 101.25,6.7 100.58,7.37 73.53,7.37 72.92,6.75 70.45,6.75 v69.9,7.3
  Top 0.4: 110.9,8.23 v113.1,8.23
  Route2 0.25: v69.9,7.3 68.7,7.3 58.2,17.8 58.2,21.4 57.5,22.1 57.5,39.9 55.6,41.8 55.6,45.4 53.6,47.4 53.6,53.9 v52.8,54.7
  Bottom 0.25: v52.8,54.7 52.1,55.4 50.7,55.4 48.3,57.8 U2.96
  Bottom 0.4: v113.1,8.23 EXT2.39
N$102  (via drill 0.4, 0.6)
  Top 0.25: v102.29,8.6 102.27,8.6 102.04,8.84 73.77,8.84 69,13.6 v65.2,13.6
  Route2 0.25: v65.2,13.6 64.6,13.6 60.9,17.3 60.9,21.5 59.5,22.9 59.5,40.7 57.6,42.6 57.6,48.85 v55.6,50.85
  Bottom 0.25: v55.6,50.85 52.55,53.9 50.8,53.9 47.9,56.8 U2.94
  Bottom 0.6: v102.29,8.6 102.65,8.23 EXT2.40
N$103
  Bottom 0.559: U5.1 45.97,4.76 45.97,5.21
  Bottom 1.27: L7.2 46.48,9.09 46.48,6.99 45.97,6.48 45.97,5.21
  Bottom 1.473: D1.A 49.31,12.61 47.55,10.85 L7.2
N$104
  Bottom 1.5: PWR_JACK.2 2.56,20.75 | 2.56,20.75 G1.AC2 | 2.56,20.75 PWR_JACK.3
N$105
  Bottom 1.5: G1.AC1 8.11,23.7 10.5,23.7 11.2,23 11.2,15.3 8.5,12.6 PWR_JACK.1
N$106
  Bottom 0.889: T3.2 53.84,16.5 53.59,16.26 53.59,13.08 | R37.2 53.59,13.08 | R5.1 53.61,13.1 53.59,13.08
N$112
  Bottom 0.6: L4.1 37.4,28.98 VREF_E.2
RASN  (via drill 0.4)
  Route2 0.25: v70.4,4.1 67.7,6.8 67.7,7.6 57.7,17.6 57.7,21.2 57,21.9 57,39.7 55.1,41.6 55.1,45.2 53.1,47.2 53.1,53.35 v51.8,54.65
  Bottom 0.25: v51.8,54.65 50.75,54.65 48.1,57.3 U2.95
  Bottom 0.4: v70.4,4.1 70.7,4.4 U4.18
RST  (via drill 0.4)
  Top 0.4: v34.92,43.2 35.33,42.8 44.4,42.8 46.1,44.5 52.7,44.5 53.3,43.9 60.4,43.9 | 60.4,43.9 v60.4,43.7 | 60.4,43.9 70.8,43.9 72.4,45.5 78.2,45.5 79.9,43.8 83.9,43.8 84.8,44.7 92.6,44.7 93.15,44.15 97.45,44.15 97.62,44.33 v99.6,44.33
  Route2 0.25: v99.6,44.33 99.6,44.9 99.2,45.3 99.2,59.4 v99.1,59.5
  Bottom 0.25: v60.4,43.7 60.4,40.1 61,39.5 61,37.3 60.5,36.8 59.2,36.8 57.8,35.4 U2.35
  Bottom 0.4: 99.5,63.6 R25.1 | RESET.P$1 96.56,63.6 C8.2 99.5,63.6 | v99.1,59.5 99.1,60.8 99.5,61.2 99.5,63.6
  Bottom 0.6: JTAG.15 34.8,44.15 34.92,44.02 v34.92,43.2
RTCK  (via drill 0.4)
  Top 0.25: v62.1,44.8 61.8,45.1 45.9,45.1 44.23,43.43 36.9,43.43 v36.54,43.8
  Bottom 0.25: v62.1,44.8 66.8,44.8 70.4,41.2 70.4,39.5 73.4,36.5 74.8,36.5 75.6,37.3 U2.206
  Bottom 0.4: RM2.1.2 v36.54,43.8 36.6,43.86 36.6,48.6 36.2,49 35.2,49 34.97,49.23
  Bottom 0.8: 34.97,49.23 JTAG.11
RXD0  (via drill 0.4, 0.6)
  Top 0.25: v4.1,50.2 4.7,49.6 15.4,49.6 18.4,46.6 26.54,46.6 28.64,44.5 34.5,44.5 35.4,45.4 44.7,45.4 45.4,46.1 70.05,46.1 v70.22,46.27
  Bottom 0.25: v70.22,46.27 70.9,45.6 70.9,39.7 73.6,37 74.6,37 75.9,38.3 U2.204
  Bottom 1: UEXT.4 4.1,49.04 v4.1,50.2
SCK  (via drill 0.4, 0.6)
  Top 0.25: v60.2,61.3 57.08,61.3 56.48,61.9 47.85,61.9 47.25,62.5 36.2,62.5 34.6,60.9 6.9,60.9 3.7,57.7 3.7,56 1.8,54.1 1.8,49.3 8.2,42.9 v8.2,40.1
  Bottom 0.25: v60.2,61.3 60.2,62.2 60.8,62.8 U2.128
  Bottom 0.4: UEXT.9 8.72,41.42 8.2,40.9 v8.2,40.1
SCL0  (via drill 0.4, 0.6)
  Top 0.25: v101.08,21.25 101.08,21.13 107.62,14.59 111.4,14.59
  Top 0.3: v87.8,66 87.7,65.9 81.4,65.9 81,66.3 65.7,66.3 v64.67,65.28
  Top 0.4: 111.4,14.59 v113.1,14.59
  Route2 0.25: v44.8,34.6 44.8,35.4 46.5,37.1 46.5,40.9 46,41.4 46,58.3 45,59.3 45,60.3 48.4,63.7 63.1,63.7 v64.67,65.28 | v87.8,66 88.3,66.5 92.1,66.5 93,65.6 93,62.5 98.2,57.3 98.2,39.3 98.7,38.8 98.7,30.4 99.1,30 99.1,23.5 101.08,21.52 v101.08,21.25
  Bottom 0.25: U2.48 51.3,35.1 50.9,35.5 48.65,35.5 46.35,33.2 45.4,33.2 44.8,33.8 v44.8,34.6 42.1,34.6 R12.2
  Bottom 0.3: U3.6 87.2,65.4 v87.8,66
  Bottom 0.6: v113.1,14.59 EXT2.29
SCL2  (via drill 0.4, 0.6)
  Top 0.25: v54.3,60.6 54,60.9 47.25,60.9 46.65,61.5 36.6,61.5 35,59.9 8,59.9 6.2,58.1 v6.2,57.2
  Bottom 0.25: v54.3,60.6 U2.115
  Bottom 0.4: 7.3,46.5 6.3,47.5 6.3,56.6
  Bottom 0.5: 7.3,46.5 UEXT.5 | 6.3,56.6 6.2,56.7 v6.2,57.2 R2.1
SDA0  (via drill 0.4)
  Route2 0.25: v101.22,17.91 100.97,17.91 100.3,18.57 100.3,21.6 98.6,23.3 98.6,29.8 98.2,30.2 98.2,38.6 97.7,39.1 97.7,57.1 92.2,62.6 v92.2,65.2 92.2,65.5 91.7,66 89.1,66 88.3,65.2 82,65.2 80.7,66.5 55.8,66.5 53.55,64.25 48.15,64.25 44.5,60.6 44.5,59.1 45.5,58.1 45.5,41.2 46,40.7 46,39.6 44,37.6 44,33.5 v44.3,33.2
  Bottom 0.2: 89.7,64.4 U3.8
  Bottom 0.25: U2.50 50.3,34.8 50.1,35 48.85,35 46.55,32.7 44.8,32.7 v44.3,33.2 41.8,33.2 R13.2 | 89.7,64.4 89.75,64.35 91.55,64.35 92.2,65 v92.2,65.2 | v101.22,17.91 102.23,17.91 103.63,16.51 104.65,16.51 105.16,16 105.16,14.77 105.34,14.59
  Bottom 0.6: 105.34,14.59 EXT2.30
SDA2  (via drill 0.6)
  Top 0.25: v36.8,63.9 36.2,63.9 34.2,61.9 5.1,61.9 2,58.8 v2,56.6
  Bottom 0.25: v36.8,63.9 38.2,65.3 40.9,65.3 42.4,63.8 46.9,63.8 48.5,65.4 50.6,65.4 51.3,64.7 U2.109
  Bottom 0.4: 4.3,46.5 5.1,47.3 5.1,52.9 2,56
  Bottom 0.5: UEXT.6 4.3,46.5 | 2,56 v2,56.6 R1.1
SDCLK  (via drill 0.4)
  Top 0.25: v41.7,17.7 50.7,17.7 51.6,16.8 53.2,16.8 53.6,16.4 69.7,16.4 v71.3,14.8
  Route2 0.25: v41.7,17.7 41.7,19.1 37.6,23.2 v37.6,36.6
  Bottom 0.25: U2.59 46.1,39.3 43.4,36.6 v37.6,36.6
  Bottom 0.4: v71.3,14.8 71.5,15 U4.38
SDCLKEN  (via drill 0.4)
  Top 0.25: v66.8,11.9 66.6,12.1 45.2,12.1 v42.8,14.5
  Route2 0.25: v42.8,14.5 44.6,16.3 44.6,31.4 46,32.8 v46,34.3
  Bottom 0.25: v46,34.3 46,35.6 46.7,36.3 U2.53
  Bottom 0.4: U4.37 70.7,15.8 v66.8,11.9
SDCS  (via drill 0.4)
  Route2 0.25: v67.7,4.1 65.1,6.7 64,6.7 55.2,15.5 55.2,20.2 53.9,21.5 53.9,33 53.5,33.4 53.5,39.6 52.6,40.5 52.6,41 v51,42.6
  Bottom 0.25: v51,42.6 51,44 48.7,46.3 U2.73
  Bottom 0.4: v67.7,4.1 69,4.1 69.9,5 U4.19
SDWEN  (via drill 0.4)
  Route2 0.25: v72.3,7.58 74.2,9.48 74.2,12.7 74.5,13 74.5,28.35 73.83,29.02 73.83,30.55 72.05,32.32 72.05,33.75 71.43,34.37 71.43,39.37 69.6,41.2 69.6,41.8 69.25,42.15 v69.25,44.73
  Bottom 0.25: U4.16 v72.3,7.58 | v69.25,44.73 69.25,47.45 70,48.2 73.7,48.2 76.3,50.8 U2.179
SSEL  (via drill 0.4, 0.6)
  Top 0.25: v5.3,54.7 7.4,56.8 7.4,58.4 8.4,59.4 35.2,59.4 35.77,59.98 43.02,59.98 44.1,58.9 60.2,58.9 v60.5,58.6
  Bottom 0.25: v60.5,58.6 61.2,59.3 61.2,60.9 61.8,61.5 U2.130
  Bottom 0.4: 5.7,42 5.7,54.3 v5.3,54.7 4.06,55.94 R23.1
  Bottom 0.5: 5.12,41.42 5.7,42
  Bottom 1: UEXT.10 5.12,41.42
TCK  (via drill 0.4, 0.6)
  Top 0.25: v67.35,56.05 67.33,56.08 59.52,56.08 58.7,56.9 39.4,56.9 v38.8,56.3
  Route2 0.25: v67.35,56.05 67,55.7 67,40.81 69.2,38.61 v69.2,37.73
  Bottom 0.25: v69.2,37.73 69.8,37.73 70.55,36.97 70.55,35.88 70.3,35.63 U2.10 70.3,33.9
  Bottom 0.4: 36.6,51.77 37.9,53.07 37.9,55 38.8,55.9 v38.8,56.3 38.8,57.59 RM1.4.2
  Bottom 0.8: JTAG.9 36.6,51.77
TDI  (via drill 0.4, 0.6)
  Top 0.25: v69.25,57.8 67.1,57.8 66.4,57.1 59.9,57.1 59.1,57.9 37.95,57.9 v36.9,56.85
  Route2 0.25: v74,35.25 74,36.15 72.43,37.72 72.43,39.77 71,41.2 71,54.55 70.67,54.88 70.67,56.38 v69.25,57.8
  Bottom 0.25: v74,35.25 73.85,35.1 73.6,35.1 73.3,34.8 U2.4
  Bottom 0.4: v36.9,56.85 37.1,57.05 37.1,58.7 37.68,59.28 RM1.2.2
  Bottom 0.8: JTAG.5 v36.9,56.85
TDO  (via drill 0.4)
  Top 0.25: v70.15,45.2 69.75,45.6 45.6,45.6 43.9,43.9 37.63,43.9 36.93,44.6 v35.8,44.6
  Route2 0.25: v70.15,45.2 70.15,41.35 71.93,39.57 71.93,34.82 74,32.75 v74,32.6
  Bottom 0.25: 36.02,41.98 35.7,42.3 35.7,44.5 v35.8,44.6 | v74,32.6 74.3,32.9 U2.2
  Bottom 0.4: v35.8,44.6 35.8,46 35.11,46.69
  Bottom 0.5: RM2.2.2 36.02,41.98
  Bottom 1: 35.11,46.69 JTAG.13
TMS  (via drill 0.4, 0.6)
  Top 0.25: v69.25,56.7 68.65,57.3 67.3,57.3 66.6,56.6 59.7,56.6 58.9,57.4 38.6,57.4 37.8,56.6 37.8,55.31 v36.8,54.31
  Route2 0.25: v69.25,56.7 69.9,56.05 69.9,54.9 68.5,53.5 68.5,41.75 v68.83,41.43
  Bottom 0.25: v68.83,41.43 68.83,40.27 72.3,36.8 U2.6
  Bottom 0.4: v36.8,54.31 36.8,55 37.9,56.1 37.9,58.3 38.12,58.52 RM1.3.2
  Bottom 0.8: JTAG.7 v36.8,54.31
TRSTN  (via drill 0.4, 0.6)
  Top 0.25: v61.62,57.88 59.83,57.88 59.3,58.4 36.3,58.4 v36.07,58.17
  Route2 0.25: v62.7,41.5 63,41.8 63,53.8 62.4,54.4 62.4,57.1 v61.62,57.88
  Bottom 0.25: v62.7,41.5 65.17,39.03 69.27,39.03 71.3,37 U2.8
  Bottom 0.4: 36.88,60.17 RM1.1.2
  Bottom 0.6: 32.31,59.39 JTAG.3
  Bottom 0.8: JTAG.3 36.07,59.39 | 36.88,60.17 36.1,59.39 36.07,59.39 | 36.07,59.39 v36.07,58.17
TXD0  (via drill 0.4)
  Top 0.25: v18.3,48.1 19.3,47.1 31.2,47.1 31.9,46.4 42.9,46.4 43.7,47.2 45.6,47.2 46.2,46.6 68.5,46.6 69.2,47.3 v70.22,47.3
  Bottom 0.25: 11.46,49.04 12.7,47.8 15.9,47.8 16.2,48.1 v18.3,48.1 | v70.22,47.3 70.6,47.3 71.4,46.5 71.4,40.9 73,39.3 U2.202
  Bottom 0.6: UEXT.3 11.46,49.04
U1D+  (via drill 0.4, 0.6)
  Route15 0.25: v45.27,40.38 44.1,39.2 28.6,39.2 20.7,47.1 v20.7,49.2
  Bottom 0.25: R34.2 17.9,54.3 18.1,54.1 18.9,54.1 20.7,52.3 v20.7,49.2 | v45.27,40.38 45.35,40.3 U2.61
  Bottom 0.8: R34.2 C10.1
U1D-  (via drill 0.4, 0.6)
  Route15 0.25: v48.75,39.85 47.45,38.55 28.15,38.55 19.8,46.9 v19.8,48.3
  Bottom 0.25: R33.2 17.3,53.6 18.5,53.6 19.8,52.3 v19.8,48.3 | U2.62 47.8,40.8 v48.75,39.85
  Bottom 0.8: R33.2 C11.1
USB1_CONNECT  (via drill 0.4)
  Top 0.25: v15.3,48.6 17.8,46.1 24.6,46.1 30.3,40.4 41.9,40.4 42.5,41 v42.75,41
  Bottom 0.25: U2.68 46,43.8 43.2,41 v42.75,41
  Bottom 0.4: R31.1 v15.3,48.6
USB_UP_LED1  (via drill 0.4, 0.6)
  Top 0.25: v42.55,40 42.45,39.9 29.9,39.9 24.2,45.6 17.1,45.6 13.8,48.9 4,48.9 2.8,50.1 2.8,53.5 3.1,53.8 7.1,53.8 v9.7,56.4
  Bottom 0.25: v42.55,40 42.9,40 45.7,42.8 U2.66 | v9.7,56.4 9.65,56.45 9.65,59.56 USB_D_LINK.C
VBUS  (via drill 0.4)
  Top 0.25: v42.65,42 42.45,42.2 34.7,42.2 32.96,43.94 27.86,43.94 v26.5,45.3
  Bottom 0.25: v42.65,42 43.5,42 45.8,44.3 U2.69
  Bottom 0.4: R32.2 23.7,45.3 v26.5,45.3
  Bottom 0.8: R35.1 R32.2
VCC  (via drill 0.4, 0.6)
  Top 0.25: v38.5,33 39.12,32.38 52.88,32.38 53.7,33.2
  Top 0.254: 53.7,33.2 53.7,36.05 v55.25,37.6
  Top 0.4: v82.8,3.8 80.1,3.8 v79.5,3.2 v74.4,3.2 64.35,3.2 v63.55,4 | v81.1,19.9 78.95,19.9 78.07,19.01 v76.5,19.01 74.33,19.01 73.44,19.9 v72.35,19.9 70.05,22.2 60.6,22.2 59.6,23.2 36.4,23.2 33.3,26.3 v33.3,27.6
  Top 0.6: v23.9,58.2 23.4,58.7 9.1,58.7 v8.3,57.9 | v40.1,63.9 47.1,63.9 47.65,64.45 53.05,64.45 53.9,63.6 59.5,63.6 59.6,63.5 78.9,63.5 79.1,63.3 93.1,63.3 93.7,63.9 v102.1,63.9 | v33.3,27.6 33.3,31.2 v30.5,34
  Route2 0.4: v76.5,19.01 76.5,8.7 74.4,6.6 v74.4,3.2
  Route2 0.6: v38.5,33 v38.5,50.5 38.5,54.4 40.1,56 v40.1,63.9
  Bottom 0.25: U3.9 88.65,63.9 C18.2 | U3.5 83.5,65.4 83.3,65.6 | C52.2 75.5,20.1 U4.43 | 81.8,3.8 81.9,3.9 | 89.7,27.3 89.5,27.1 LCD.4 | 91,27.3 91.57,27.87 91.57,30.1 91.85,30.39
  Bottom 0.253: 91,27.3 89.7,27.3
  Bottom 0.254: v55.25,37.6 55.55,37.6 56.5,36.65 56.5,35.2 56.3,35 U2.38
  Bottom 0.4: 41.3,60.17 RM1.1.1 | 41.3,59.28 RM1.2.1 | 41.3,58.52 RM1.3.1 | v38.5,50.5 38.5,47.2 38.7,47 38.7,42.87 | 38.7,42.87 RM2.1.1 | 38.58,41.98 38.7,42.1 38.7,42.87 | 83.3,65.6 83.3,66.5 83.7,66.9 93.1,66.9 | C18.2 89.25,63.8 92.2,63.8 93.1,64.7 93.1,66.9 | 80.3,19.9 U4.49 | 81.9,3.9 81.9,4.3 82.7,5.1 U4.3 | U4.14 73.9,5.1 C41.2 75.2,3.2 v74.4,3.2 | U4.27 63.5,10.3 62.9,10.9 C40.2 61.7,10.6 61.7,10.1 62.4,9.4 62.4,4 | 81.92,3.8 v82.8,3.8 v82.81,3.81 83.61,3.81 C37.2 83.9,3.64 84.3,4.04 U4.1 | 81.92,3.8 81.8,3.8 | 62.4,4 62.4,3.5 R24.2 | v81.1,19.9 80.3,19.9 | 80.3,19.9 C42.2 | v72.35,19.9 72.05,20.2 VDDA_E.1 | T1.2 96.5,39.4 R4.1 99.2,39.4 99.4,39.6 99.4,40.5 100.5,41.6 100.5,42.5 | 100.5,42.5 98.72,42.5 98.4,42.82 PWR.A | 99.9,45.6 100.5,45 100.5,42.5 | 97.9,66.9 99.6,66.9 99.7,66.8 | v63.55,4 62.4,4 | 37.4,32.9 VREF_E.1 | 97.9,66.9 3.3V_E.1 | 97.9,66.9 93.1,66.9 | R44.2 92.4,37.7 92.9,37.7 93.2,37.4 93.2,31.73 | U4.9 77.9,5.03 78.5,4.43 C38.2 78.54,3.5 78.84,3.2 v79.5,3.2 | C52.2 75.81,20.2 76.5,19.51 v76.5,19.01 | 81.92,3.8 81.92,3.81 81.61,3.5 C39.2 | 93.2,31.73 91.85,30.39 | 93.2,31.73 93.22,31.75 94.74,31.75 95,31.5
  Bottom 0.5: R27.1 15.1,53.2 T5.2 | 38.58,41.98 RM2.2.1
  Bottom 0.508: R27.1 10.9,53.2 8.3,55.8 v8.3,57.9 8.3,60.88 3.3V_UEXT_E.2 7.18,64.71 7.75,65.28 9.56,65.28 R3.2
  Bottom 0.6: 41.3,61.1 41.3,60.2 | 41.3,60.2 41.3,60.17 | 41.3,60.2 41.3,59.3 | 41.3,59.3 41.3,59.28 | 41.3,59.3 41.3,58.52 | 99.9,51.62 L3.2 | 101.3,59.37 EXT1.2 | 101.3,59.37 101.3,61.9 R25.2 100.8,62.1 101.5,62.1 102.1,62.7 v102.1,63.9 102.1,64.4 99.7,66.8 | 101.3,59.37 101.3,57.2 99.9,55.8 99.9,51.62 | C33.+ v33.3,27.6 | 99.9,51.62 99.9,45.6
  Bottom 0.66: C2.1 95.73,31.47 96.63,32.37 96.65,32.37 | 96.65,32.37 EXT2.2 | T1.2 96.77,39.3 96.77,32.51 96.65,32.38 96.65,32.37
  Bottom 0.8: C33.+ 32.5,30.1 32,30.6 32,32.2 | 14.8,36.8 R43.2 | 14.8,36.8 VR1(3.3V).4 | VR1(3.3V).2 14.8,33.5 14.8,36.8 | v23.9,58.2 23.9,61.6 24.23,61.93 JTAG.2 JTAG.1 40.1,61.93 | 40.1,61.93 40.47,61.93 41.3,61.1 | R42.2 39.5,51.3 38.7,50.5 v38.5,50.5 | 32,32.2 32.7,32.9 37.4,32.9 38.5,32.9 v38.5,33 R13.1 R12.1 | v40.1,63.9 40.1,61.93 | 32,32.2 23.69,32.2 23.3,31.8 C34.2 23.14,31.75 20.28,31.75 C4.2
  Bottom 1: 14.8,33.5 14.8,32.3 15.86,31.24 18.54,31.24 19.27,31.96 C4.2
  Bottom 1.016: C2.1 95.57,31.5 95,31.5
  other vias: 17.5,38.5 19,38.5 20.5,38.5 27.5,35.5 27.5,34 29,35.5 29,34 17.5,40 19,40 20.5,40 22,38.5 30.5,35.5 26,35.5 26,34 23.5,34 23.5,35.5
  pour Route2 (isolate 0.406, rank 6): -3,70.5 118,70.5 118,-3 -3,-3
  pour Bottom (isolate 0.4, rank 2, no thermals): 9.61,42.5 9.61,30.5 39.5,30.5 39.5,36.5 38.5,37.5 29,37.5 24,42.5
  pour Top (isolate 0.4, rank 2, no thermals): 14,42 14,32.5 32,32.5 32,36 31,37 28.5,37 23.5,42
VDC_DC  (via drill 0.4)
  Top 0.4: v40.6,50.1 49.4,50.1 50.8,48.7 61.4,48.7 62.27,49.58 76.65,49.58 77.92,50.85 v82.6,50.85 | v38.7,31.6 38.7,29.4 39.52,28.57 v60.27,28.57
  Route2 0.25: v60.27,35.45 60,35.17 60,28.85 v60.27,28.57
  Route2 0.4: v40.6,50.1 40.6,46.3 39.2,44.9 39.2,35.1 39.4,34.9 39.4,32.3 v38.7,31.6
  Bottom 0.25: C36.2 80.8,53.3 U2.174 | U2.86 45.9,52.8 44.4,51.3 R42.1 | 41.78,49.08 C35.2 | v60.27,35.45 61.65,35.45 62.3,34.8 U2.26 | 41.78,50.1 41.78,50.09
  Bottom 0.4: 41.78,49.08 41.78,50.09 R42.1 | v40.6,50.1 41.78,50.1 | v82.6,50.85 82.5,50.95 82.5,51.6 C36.2 | v60.27,28.57 60,28.85 C30.2
X1  (via drill 0.4)
  Route2 0.25: v73.2,24.58 72.33,25.45 72.33,29.41 v72.07,29.67
  Bottom 0.25: v72.07,29.67 72.07,30.37 71.32,31.11 68.28,31.11 67.3,32.1 U2.16 | v73.2,24.58 73,24.78 LCD.37
X2  (via drill 0.4)
  Route2 0.25: v62.82,23.05 62.87,23.1 62.87,32 63.25,32.38 63.25,33.85 62.5,34.6 62.5,40.5 59.6,43.4 v59.6,55.35
  Bottom 0.25: LCD.39 72,25.56 69.49,23.05 v62.82,23.05 | v59.6,55.35 55.05,59.9 55.05,60.95 54.8,61.2 U2.116
Y1  (via drill 0.4)
  Route2 0.25: v72.07,24.46 71.7,24.83 71.7,27.77 71.25,28.23 71.25,30.1 v71,30.34
  Bottom 0.25: U2.18 66.3,32.15 67.93,30.52 70.83,30.52 v71,30.34 | v72.07,24.46 72.07,24.84 72.5,25.26 LCD.38
Y2  (via drill 0.4)
  Route2 0.25: v61.25,23.05 61.47,23.27 61.47,29.21 61.09,29.59 61.09,34.42 61.5,34.83 61.5,40.1 58.6,43 58.6,54.4 55.8,57.2 v55.8,60.6
  Bottom 0.25: v61.25,23.05 62,23.8 69.46,23.8 71.5,25.84 LCD.40 | v55.8,60.6 U2.118

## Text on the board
Top: 4 LAYERS PCB | BEZ TOP SILK
Bottom: 23 errors :)
bNames: RoHS Compliant | (C) 2016 | + | HTTPS://WWW.OLIMEX.COM | Rev.B | LCD | MOD-LCD4.3''+ | 6-9VAC | 9-12VDC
